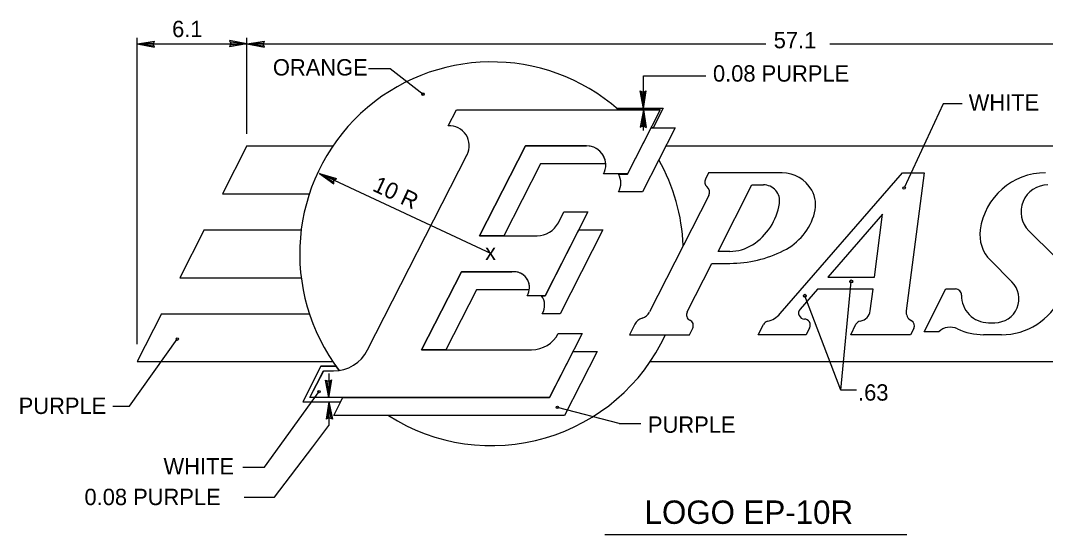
# Model space of a CAD drawing. Extents: x 10268197 to 10269179, y 2141503 to 2142677.
# Drawn here: x 10268854.11 to 10268891.94, y 2142124.85 to 2142143.81 of the extents above; entities that cross this region are included whole.
import ezdxf

# ---------------------------------------------------------------- set-up
doc = ezdxf.new("R2010")
doc.units = 0
for name, color, linetype in [('1', 7, 'Continuous'), ('Default', 7, 'Continuous'), ('TextDetails', 7, 'Continuous')]:
    doc.layers.add(name, color=color, linetype=linetype)

msp = doc.modelspace()

# ---------------------------------------------------------------- linework, layer by layer
at = {"layer": '1'}
for p, q in [((10268858.418, 2142131.872), (10268858.418, 2142143.168)), ((10268858.418, 2142142.948), (10268881.62, 2142142.948)), ((10268862.472, 2142139.629), (10268862.472, 2142143.168)), ((10268883.975, 2142142.948), (10268903.175, 2142142.948)), ((10268866.95, 2142142.036), (10268867.75, 2142142.036)), ((10268867.75, 2142142.036), (10268868.971, 2142141.094)), ((10268877.098, 2142141.77), (10268879.406, 2142141.77)), ((10268877.098, 2142140.599), (10268877.098, 2142141.77)), ((10268888.16, 2142140.738), (10268886.72, 2142137.631)), ((10268888.862, 2142140.738), (10268888.16, 2142140.738)), ((10268877.098, 2142139.757), (10268877.098, 2142140.52)), ((10268871.497, 2142135.205), (10268865.145, 2142138.167)), ((10268884.384, 2142130.166), (10268884.77, 2142134.185)), ((10268884.384, 2142130.166), (10268883.055, 2142133.656)), ((10268858.14, 2142129.576), (10268859.898, 2142132.055)), ((10268865.496, 2142130.782), (10268865.496, 2142129.902)), ((10268863.122, 2142127.332), (10268865.129, 2142130.121)), ((10268884.956, 2142130.166), (10268884.384, 2142130.166)), ((10268865.496, 2142129.745), (10268865.496, 2142128.873)), ((10268857.527, 2142129.576), (10268858.14, 2142129.576)), ((10268876.2, 2142128.94), (10268873.927, 2142129.535)), ((10268864.896, 2142128.08), (10268865.496, 2142128.873)), ((10268876.2, 2142128.94), (10268877.001, 2142128.94)), ((10268863.492, 2142126.227), (10268864.896, 2142128.08)), ((10268862.321, 2142127.332), (10268863.122, 2142127.332)), ((10268862.368, 2142126.227), (10268863.492, 2142126.227))]:
    msp.add_line(p, q, dxfattribs=at)
for centre, radius in [((10268868.97, 2142141.093), 0.0442), ((10268886.72, 2142137.63), 0.0442), ((10268884.77, 2142134.185), 0.0518), ((10268883.055, 2142133.656), 0.0518), ((10268859.898, 2142132.054), 0.0442), ((10268865.129, 2142130.12), 0.0442), ((10268873.927, 2142129.534), 0.0442)]:
    msp.add_circle(centre, radius, dxfattribs=at)
at = {"layer": 'Default'}
for p, q in [((10268858.418, 2142142.948), (10268859.065, 2142143.05)), ((10268858.418, 2142142.948), (10268859.038, 2142142.99)), ((10268858.418, 2142142.948), (10268859.061, 2142142.822)), ((10268858.418, 2142142.948), (10268859.036, 2142142.882)), ((10268859.013, 2142142.937), (10268859.065, 2142143.05)), ((10268859.061, 2142142.822), (10268859.013, 2142142.937)), ((10268861.876, 2142142.957), (10268861.825, 2142142.845)), ((10268862.472, 2142142.948), (10268861.825, 2142142.845)), ((10268862.472, 2142142.948), (10268861.829, 2142143.072)), ((10268861.829, 2142143.072), (10268861.876, 2142142.957)), ((10268862.472, 2142142.948), (10268861.853, 2142142.904)), ((10268862.472, 2142142.948), (10268861.854, 2142143.012)), ((10268862.472, 2142142.948), (10268863.119, 2142143.05)), ((10268862.472, 2142142.948), (10268863.091, 2142142.99)), ((10268862.472, 2142142.948), (10268863.115, 2142142.822)), ((10268862.472, 2142142.948), (10268863.09, 2142142.882)), ((10268863.067, 2142142.937), (10268863.119, 2142143.05)), ((10268863.115, 2142142.822), (10268863.067, 2142142.937)), ((10268877.099, 2142140.568), (10268876.975, 2142141.211)), ((10268876.975, 2142141.211), (10268877.09, 2142141.164)), ((10268877.099, 2142140.568), (10268877.035, 2142141.187)), ((10268877.09, 2142141.164), (10268877.202, 2142141.215)), ((10268877.099, 2142140.568), (10268877.202, 2142141.215)), ((10268877.099, 2142140.568), (10268877.143, 2142141.188)), ((10268876.103, 2142140.58), (10268877.827, 2142140.58)), ((10268877.827, 2142140.58), (10268877.455, 2142139.851)), ((10268869.896, 2142139.92), (10268870.198, 2142140.514)), ((10268870.198, 2142140.514), (10268877.719, 2142140.514)), ((10268877.719, 2142140.514), (10268876.515, 2142138.149)), ((10268877.099, 2142140.515), (10268876.975, 2142139.872)), ((10268877.099, 2142140.515), (10268877.035, 2142139.897)), ((10268877.099, 2142140.515), (10268877.202, 2142139.869)), ((10268877.099, 2142140.515), (10268877.143, 2142139.896)), ((10268876.513, 2142138.146), (10268877.382, 2142139.851)), ((10268876.513, 2142138.146), (10268877.382, 2142139.851)), ((10268876.975, 2142139.872), (10268877.09, 2142139.92)), ((10268878.276, 2142139.851), (10268877.07, 2142137.485)), ((10268878.276, 2142139.851), (10268877.07, 2142137.485)), ((10268877.09, 2142139.92), (10268877.202, 2142139.869)), ((10268877.382, 2142139.851), (10268878.276, 2142139.851)), ((10268877.382, 2142139.851), (10268878.276, 2142139.851)), ((10268862.472, 2142139.187), (10268861.571, 2142137.417)), ((10268862.472, 2142139.187), (10268865.644, 2142139.187)), ((10268872.747, 2142139.187), (10268871.057, 2142135.869)), ((10268871.057, 2142135.869), (10268872.747, 2142139.187)), ((10268871.057, 2142135.869), (10268872.747, 2142139.187)), ((10268875.002, 2142139.187), (10268872.747, 2142139.187)), ((10268872.747, 2142139.187), (10268875.002, 2142139.187)), ((10268872.747, 2142139.187), (10268875.002, 2142139.187)), ((10268877.937, 2142139.187), (10268903.175, 2142139.187)), ((10268866.924, 2142131.654), (10268870.596, 2142138.861)), ((10268873.303, 2142138.523), (10268871.95, 2142135.869)), ((10268873.303, 2142138.523), (10268871.95, 2142135.869)), ((10268875.71, 2142138.523), (10268873.303, 2142138.523)), ((10268875.71, 2142138.523), (10268873.303, 2142138.523)), ((10268865.145, 2142138.167), (10268865.774, 2142137.987)), ((10268865.145, 2142138.167), (10268865.674, 2142137.783)), ((10268865.145, 2142138.167), (10268865.677, 2142137.847)), ((10268865.145, 2142138.167), (10268865.724, 2142137.945)), ((10268865.68, 2142137.906), (10268865.774, 2142137.987)), ((10268876.515, 2142138.149), (10268875.629, 2142138.149)), ((10268876.184, 2142138.146), (10268876.513, 2142138.146)), ((10268876.184, 2142138.146), (10268876.513, 2142138.146)), ((10268879.505, 2142138.191), (10268879.385, 2142137.955)), ((10268882.214, 2142138.191), (10268879.505, 2142138.191)), ((10268882.147, 2142132.995), (10268886.665, 2142138.191)), ((10268886.665, 2142138.191), (10268887.461, 2142138.191)), ((10268887.461, 2142138.191), (10268886.799, 2142133.1)), ((10268865.674, 2142137.783), (10268865.68, 2142137.906)), ((10268879.852, 2142135.293), (10268881.104, 2142137.749)), ((10268881.104, 2142137.749), (10268881.53, 2142137.749)), ((10268861.571, 2142137.417), (10268864.773, 2142137.417)), ((10268877.07, 2142137.485), (10268876.185, 2142137.485)), ((10268877.07, 2142137.485), (10268876.185, 2142137.485)), ((10268879.513, 2142137.355), (10268877.322, 2142133.056)), ((10268875.051, 2142136.754), (10268873.474, 2142133.657)), ((10268873.962, 2142136.351), (10268874.166, 2142136.754)), ((10268874.166, 2142136.754), (10268875.051, 2142136.754)), ((10268885.924, 2142136.665), (10268883.904, 2142134.342)), ((10268885.621, 2142134.342), (10268885.924, 2142136.665)), ((10268860.896, 2142136.09), (10268859.995, 2142134.32)), ((10268860.896, 2142136.09), (10268864.473, 2142136.09)), ((10268873.474, 2142133.657), (10268874.713, 2142136.09)), ((10268873.474, 2142133.657), (10268874.713, 2142136.09)), ((10268875.607, 2142136.09), (10268874.029, 2142132.993)), ((10268875.607, 2142136.09), (10268874.029, 2142132.993)), ((10268874.713, 2142136.09), (10268875.607, 2142136.09)), ((10268874.713, 2142136.09), (10268875.607, 2142136.09)), ((10268891.322, 2142136.049), (10268892.25, 2142135.122)), ((10268871.057, 2142135.869), (10268873.173, 2142135.869)), ((10268871.95, 2142135.869), (10268871.057, 2142135.869)), ((10268871.95, 2142135.869), (10268871.057, 2142135.869)), ((10268880.291, 2142135.293), (10268879.852, 2142135.293)), ((10268890.697, 2142134.171), (10268889.901, 2142134.967)), ((10268870.381, 2142134.541), (10268868.915, 2142131.665)), ((10268868.915, 2142131.665), (10268870.381, 2142134.541)), ((10268868.915, 2142131.665), (10268870.381, 2142134.541)), ((10268872.322, 2142134.541), (10268870.381, 2142134.541)), ((10268870.381, 2142134.541), (10268872.239, 2142134.535)), ((10268870.381, 2142134.541), (10268872.239, 2142134.535)), ((10268878.712, 2142133.056), (10268879.627, 2142134.851)), ((10268879.627, 2142134.851), (10268880.291, 2142134.851)), ((10268859.995, 2142134.32), (10268864.473, 2142134.32)), ((10268883.904, 2142134.342), (10268885.621, 2142134.342)), ((10268870.935, 2142133.876), (10268869.809, 2142131.665)), ((10268870.935, 2142133.876), (10268869.809, 2142131.665)), ((10268872.889, 2142133.87), (10268870.935, 2142133.876)), ((10268872.889, 2142133.87), (10268870.935, 2142133.876)), ((10268883.521, 2142133.899), (10268882.879, 2142133.162)), ((10268885.576, 2142133.899), (10268883.521, 2142133.899)), ((10268885.471, 2142133.1), (10268885.576, 2142133.899)), ((10268887.458, 2142132.329), (10268888.261, 2142133.906)), ((10268888.261, 2142133.906), (10268888.616, 2142133.906)), ((10268873.474, 2142133.657), (10268872.807, 2142133.657)), ((10268873.334, 2142133.657), (10268873.474, 2142133.657)), ((10268873.334, 2142133.657), (10268873.474, 2142133.657)), ((10268859.319, 2142132.993), (10268858.418, 2142131.223)), ((10268859.319, 2142132.993), (10268864.773, 2142132.993)), ((10268874.029, 2142132.993), (10268873.365, 2142132.993)), ((10268874.029, 2142132.993), (10268873.365, 2142132.993)), ((10268889.833, 2142132.66), (10268890.072, 2142132.66)), ((10268874.842, 2142132.261), (10268873.637, 2142129.896)), ((10268873.957, 2142132.261), (10268874.842, 2142132.261)), ((10268876.784, 2142132.609), (10268876.586, 2142132.218)), ((10268878.798, 2142132.218), (10268878.918, 2142132.455)), ((10268881.333, 2142132.218), (10268881.525, 2142132.597)), ((10268883.233, 2142132.474), (10268883.102, 2142132.218)), ((10268884.747, 2142132.218), (10268884.943, 2142132.603)), ((10268887.075, 2142132.446), (10268886.959, 2142132.218)), ((10268887.996, 2142132.329), (10268887.458, 2142132.329)), ((10268876.586, 2142132.218), (10268878.798, 2142132.218)), ((10268883.102, 2142132.218), (10268881.333, 2142132.218)), ((10268886.959, 2142132.218), (10268884.747, 2142132.218)), ((10268890.31, 2142132.218), (10268889.644, 2142132.218)), ((10268868.915, 2142131.665), (10268872.976, 2142131.665)), ((10268869.809, 2142131.665), (10268868.915, 2142131.665)), ((10268869.809, 2142131.665), (10268868.915, 2142131.665)), ((10268873.637, 2142129.896), (10268874.504, 2142131.598)), ((10268873.637, 2142129.896), (10268874.504, 2142131.598)), ((10268875.398, 2142131.598), (10268874.192, 2142129.232)), ((10268875.398, 2142131.598), (10268874.192, 2142129.232)), ((10268874.504, 2142131.598), (10268875.398, 2142131.598)), ((10268874.504, 2142131.598), (10268875.398, 2142131.598)), ((10268858.418, 2142131.223), (10268865.644, 2142131.223)), ((10268877.35, 2142131.223), (10268899.117, 2142131.223)), ((10268865.198, 2142131.054), (10268864.532, 2142129.745)), ((10268864.789, 2142129.896), (10268865.291, 2142130.881)), ((10268865.198, 2142131.054), (10268865.763, 2142131.054)), ((10268865.291, 2142130.881), (10268865.662, 2142130.881)), ((10268865.496, 2142129.902), (10268865.371, 2142130.545)), ((10268865.371, 2142130.545), (10268865.486, 2142130.498)), ((10268865.496, 2142129.902), (10268865.432, 2142130.52)), ((10268865.486, 2142130.498), (10268865.599, 2142130.549)), ((10268865.496, 2142129.902), (10268865.599, 2142130.549)), ((10268865.496, 2142129.902), (10268865.539, 2142130.522)), ((10268864.532, 2142129.745), (10268865.92, 2142129.745)), ((10268873.637, 2142129.896), (10268864.789, 2142129.896)), ((10268865.496, 2142129.745), (10268865.394, 2142129.099)), ((10268865.496, 2142129.745), (10268865.453, 2142129.126)), ((10268865.496, 2142129.745), (10268865.621, 2142129.102)), ((10268865.496, 2142129.745), (10268865.561, 2142129.127)), ((10268865.673, 2142129.232), (10268866.011, 2142129.896)), ((10268865.673, 2142129.232), (10268866.011, 2142129.896)), ((10268866.011, 2142129.896), (10268873.637, 2142129.896)), ((10268866.011, 2142129.896), (10268873.637, 2142129.896)), ((10268865.506, 2142129.15), (10268865.394, 2142129.099)), ((10268865.621, 2142129.102), (10268865.506, 2142129.15)), ((10268874.192, 2142129.232), (10268865.673, 2142129.232)), ((10268874.192, 2142129.232), (10268865.673, 2142129.232)), ((10268875.67, 2142124.845), (10268886.819, 2142124.845))]:
    msp.add_line(p, q, dxfattribs=at)
for points in [[(10268876.103, 2142140.58), (10268877.827, 2142140.58), (10268877.455, 2142139.851), (10268877.382, 2142139.851), (10268877.719, 2142140.514), (10268876.179, 2142140.513)], [(10268865.763, 2142131.054), (10268865.198, 2142131.054), (10268864.532, 2142129.745), (10268865.92, 2142129.745), (10268866.011, 2142129.896), (10268864.789, 2142129.896), (10268865.304, 2142130.881), (10268865.667, 2142130.881), (10268865.879, 2142130.898)]]:
    msp.add_lwpolyline(points, close=True, dxfattribs=at)
for centre, radius, start, end in [((10268871.497, 2142135.204), 7.079, 48.5904, 217.4727), ((10268869.945, 2142139.192), 0.73, 332.9998, 93.8045), ((10268875.003, 2142138.478), 0.708, 332.2089, 90), ((10268875.003, 2142138.478), 0.708, 3.5833, 90), ((10268875.003, 2142138.478), 0.708, 3.5833, 90), ((10268871.497, 2142135.204), 7.079, 2.4236, 29.2771), ((10268875.558, 2142137.814), 0.708, 332.2089, 27.9127), ((10268875.558, 2142137.814), 0.708, 332.2089, 27.9127), ((10268879.581, 2142137.854), 0.221, 152.9784, 231.1602), ((10268882.214, 2142136.93), 1.261, 29.4315, 90), ((10268891.936, 2142135.757), 2.433, 90, 172.3089), ((10268879.276, 2142137.475), 0.265, 333.0027, 51.1602), ((10268881.53, 2142137.151), 0.597, 351.076, 90), ((10268892.026, 2142136.753), 0.995, 90, 225), ((10268882.349, 2142137.006), 1.106, 344.7074, 29.4315), ((10268879.935, 2142137.401), 2.212, 302.4206, 351.076), ((10268881.282, 2142137.297), 2.212, 296.6431, 344.7074), ((10268873.173, 2142136.753), 0.885, 270, 332.9883), ((10268890.84, 2142135.905), 1.327, 172.3089, 225), ((10268880.29, 2142136.841), 1.548, 270, 302.4206), ((10268880.29, 2142139.274), 4.424, 270, 296.6431), ((10268872.322, 2142133.965), 0.575, 350.3502, 98.3344), ((10268872.322, 2142133.965), 0.575, 350.3502, 98.3344), ((10268872.322, 2142133.965), 0.575, 327.421, 90), ((10268890.071, 2142133.545), 0.885, 270, 45), ((10268888.616, 2142133.684), 0.221, 358.6664, 90), ((10268872.881, 2142133.302), 0.575, 327.421, 37.9799), ((10268872.881, 2142133.302), 0.575, 327.421, 37.9799), ((10268889.833, 2142133.656), 0.995, 178.6665, 270), ((10268890.309, 2142134.651), 2.433, 270, 334.95), ((10268876.928, 2142133.256), 0.442, 286.4317, 332.9959), ((10268878.909, 2142132.955), 0.221, 152.9884, 244.7832), ((10268883.046, 2142133.016), 0.221, 138.9824, 268.6869), ((10268885.033, 2142133.156), 0.442, 279.2397, 352.5632), ((10268887.149, 2142133.053), 0.354, 172.5884, 241.8673), ((10268877.178, 2142132.407), 0.442, 106.4317, 152.9742), ((10268878.72, 2142132.555), 0.221, 333.0239, 64.7832), ((10268881.723, 2142132.496), 0.221, 102.7162, 153.0239), ((10268881.479, 2142133.575), 0.885, 282.7162, 318.9966), ((10268883.036, 2142132.574), 0.221, 332.9784, 88.6869), ((10268885.139, 2142132.501), 0.221, 99.2397, 153.0239), ((10268886.878, 2142132.546), 0.221, 332.9784, 61.8673), ((10268872.975, 2142132.771), 1.106, 270, 332.5096), ((10268888.419, 2142131.877), 0.619, 64.3795, 133.1892), ((10268889.644, 2142134.43), 2.212, 244.3795, 270), ((10268871.497, 2142135.204), 7.079, 237.5383, 335.047), ((10268865.662, 2142132.297), 1.416, 270, 332.9991)]:
    msp.add_arc(centre, radius, start, end, dxfattribs=at)

# ---------------------------------------------------------------- texts
at = {"layer": '1'}
for s, height, p in [('6.1', 0.6037, (10268859.709, 2142143.199)), ('57.1', 0.6037, (10268881.907, 2142142.786)), ('ORANGE', 0.6037, (10268863.428, 2142141.782)), ('0.08 PURPLE', 0.60368, (10268879.666, 2142141.556)), ('WHITE', 0.6037, (10268889.102, 2142140.487)), ('x', 0.604, (10268871.257, 2142134.969)), ('.63', 0.6037, (10268885.02, 2142129.785)), ('PURPLE', 0.6037, (10268854.048, 2142129.293)), ('PURPLE', 0.6037, (10268877.267, 2142128.599)), ('WHITE', 0.6037, (10268859.392, 2142127.06)), ('0.08 PURPLE', 0.60368, (10268856.475, 2142125.93))]:
    msp.add_text(s, height=height, dxfattribs=at).set_placement(p)
msp.add_text('10 R', height=0.6037, rotation=334.9991, dxfattribs=at).set_placement((10268867.066, 2142137.545))
at = {"layer": 'TextDetails'}
msp.add_text('LOGO EP-10R', height=0.8624, dxfattribs=at).set_placement((10268877.143, 2142125.238))

doc.saveas('drawing.dxf')
